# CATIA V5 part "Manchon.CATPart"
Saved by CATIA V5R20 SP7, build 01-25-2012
Part number: Manchon
Bounding box of the stored display mesh (mm): x -21 to 21, y -21 to 21, z 0 to 80
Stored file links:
  F:\Travaux\Modélisations\CFAO_2011\MMS\MMS_GR1\AA_OK\bmadec\Catia\Manchon.CATPart
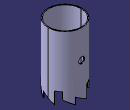
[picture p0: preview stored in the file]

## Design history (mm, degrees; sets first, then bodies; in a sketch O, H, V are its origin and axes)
Set1
  Plane1: type Angle, RefPlane yz-plane, Direction Z axis, Angle 45
Body1 (main body)
  Sketch1 on xy-plane, origin (0, 0, 0), H (1, 0, 0), V (0, 1, 0)
    circle A1 centre (0, 0) radius 21
    circle A2 centre (0, 0) radius 20
    radius A1 = 21
    distance A2 A1 = 1
  Pad1: profile Sketch1, direction (0, 0, 1), length 80
  Sketch2 on yz-plane, origin (0, 0, 0), H (0, 1, 0), V (0, 0, 1)
    point P1 (6.95, 0)
    line L1 (6.95, 0) -> (-6.95, 8.0252)
    line L2 (-6.95, 8.0252) -> (-6.95, 0)
    point P3 (-6.95, 0)
    line L3 (-6.95, 0) -> (6.95, 0)
    angle L3 L1 = 30
    distance V L2 = 6.95
    coincidence: P1 H, P3 H
    vertical: L2 V
    horizontal: L3 H
    symmetry: P1 P3 V
  Pocket1: profile Sketch2, direction (1, 0, 0), up to face of Pad1 from Sketch1.A1
  CircPattern1: of Pocket1, instances 4, angular step 90, axis from face of Pad1 from Sketch1.A1
  Sketch3 on Plane1, origin (0, 0, 0), H (-0.7071, 0.7071, 0), V (0, 0, 1)
    point P1 (-9.0981, 0)
    line L1 (-9.0981, 0) -> (-9.0981, 15)
    line L2 (-9.0981, 15) -> (-2.1481, 15)
    line L3 (-2.1481, 15) -> (-2.1481, 6.4929)
    line L4 (-2.1481, 6.4929) -> (9.0981, 0)
    point P5 (9.0981, 0)
    line L5 (9.0981, 0) -> (-9.0981, 0)
    reference projected point E1 (-9.0981, 0) from vertex [face of Pad1 from Sketch1.A1 | start face of Pad1 | face of Pocket1 from Sketch2.L1]
    reference projected point E2 (9.0981, 0) from vertex [face of CircPattern1 | start face of Pad1 | face of Pad1 from Sketch1.A1]
    length L2 = 6.95
    angle L4 L5 = 30
    length L1 = 15
    coincidence: P1 H, P5 H, E1 P1, P5 E2
    vertical: L1 V, L3 V
    horizontal: L2 H, L5 H
  Pocket2: profile Sketch3, direction (0.7071, 0.7071, 0), up to face of Pad1 from Sketch1.A1
  CircPattern2: of Pocket2, instances 4, angular step 90, axis from face of Pad1 from Sketch1.A1
  Sketch4 on {plane type Tangent, Support face of Pad1 from Sketch1.A1, RefPoint {point type OnSurface, Support face of Pad1 from Sketch1.A1, RefPoint {point stored without definition}, Length 0, Direction (0, 0, 1000)}}, origin (1.2506, -20.9627, 57.6584), H (0.9982, 0.0596, 0), V (0, 0, -1)
    point P1 (-1.2529, 12.6584)
    reference intersected line E1 through (-1.2529, 0) direction (0, 1) from yz-plane
    reference projected line E2 (21, -22.3416) -> (-21, -22.3416) from edge [face of Pad1 from Sketch1.A1 | end face of Pad1]
    distance P1 E2 = 35
    coincidence: P1 E1
  Hole1: placed by Sketch4, at (0, -21, 45) direction (0, 1, 0), diameter 7.5, up to face of Pad1 from Sketch1.A1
